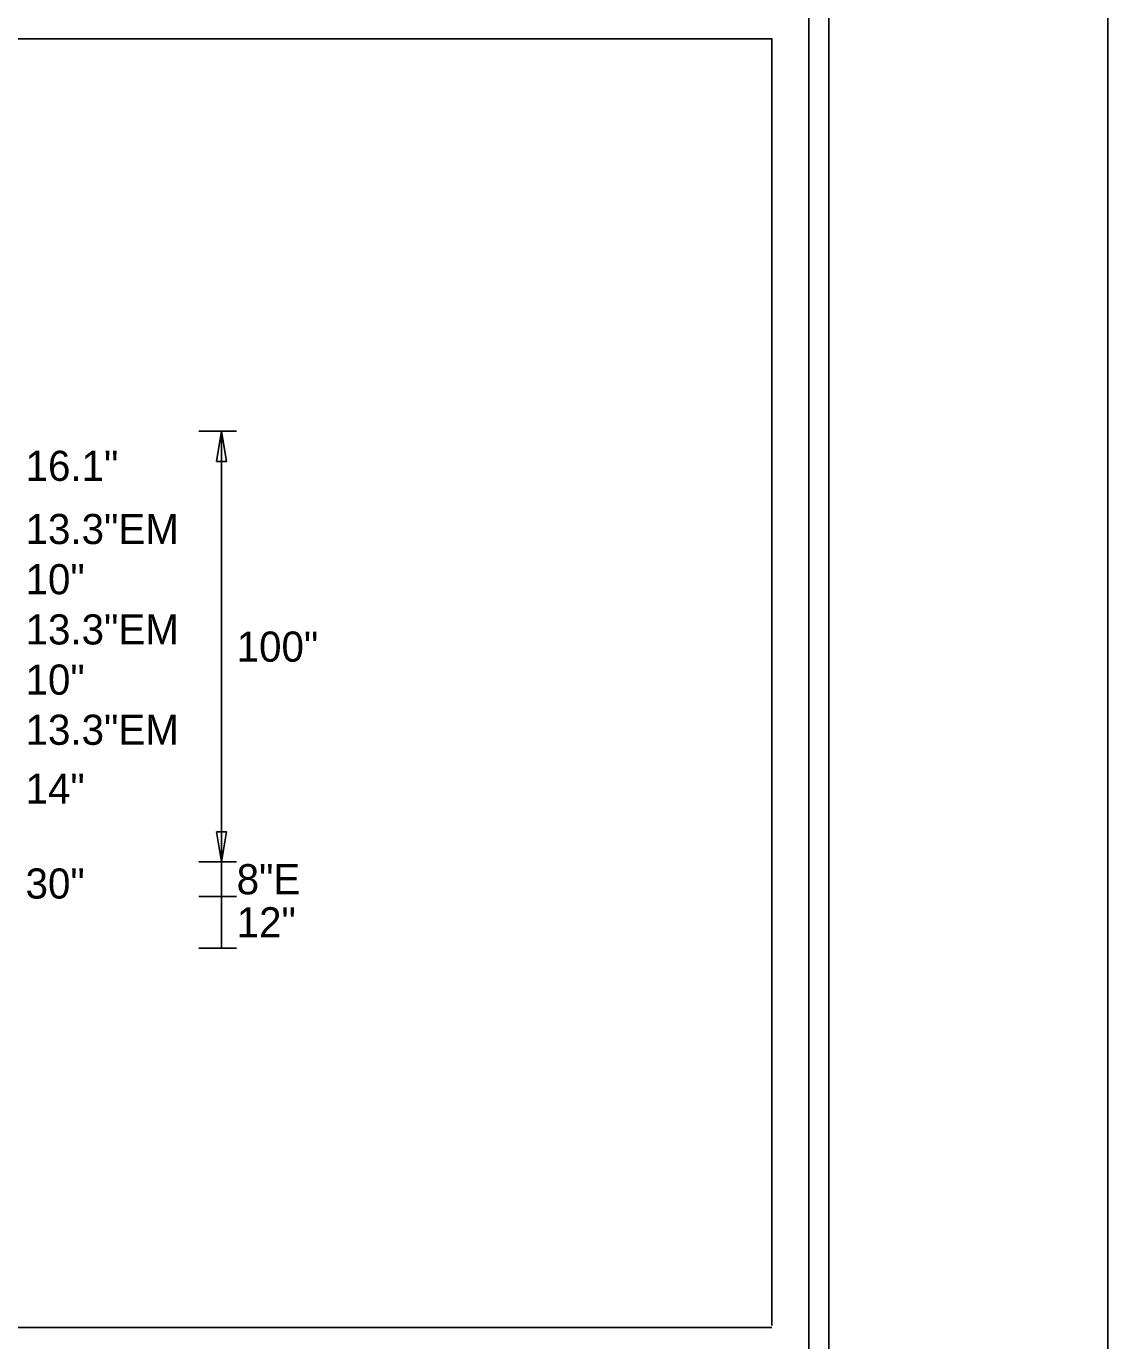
# Model space of a CAD drawing. Extents: x 17890628 to 17890817, y 17897493 to 17897992.
# Drawn here: x 17890796.4 to 17890817.32, y 17897520.28 to 17897545.71 of the extents above; entities that cross this region are included whole.
import ezdxf

# ---------------------------------------------------------------- set-up
doc = ezdxf.new("R2010")
doc.units = 0
for name, color, linetype in [('GSDims', 7, 'Continuous'), ('PlotBorder_dp', 7, 'Continuous'), ('SheetBorder_dp', 7, 'Continuous'), ('SheetLinesMisc1_dp', 7, 'Continuous'), ('SheetLinesMisc2_dp', 7, 'Continuous')]:
    doc.layers.add(name, color=color, linetype=linetype)

msp = doc.modelspace()

# ---------------------------------------------------------------- linework, layer by layer
at = {"layer": 'GSDims'}
for p, q in [((17890799.743, 17897537.876), (17890800.472, 17897537.876)), ((17890800.18, 17897529.543), (17890800.18, 17897537.876)), ((17890799.743, 17897529.543), (17890800.472, 17897529.543)), ((17890799.743, 17897529.543), (17890800.472, 17897529.543)), ((17890800.18, 17897529.543), (17890800.18, 17897528.876)), ((17890799.743, 17897528.876), (17890800.472, 17897528.876)), ((17890799.743, 17897528.876), (17890800.472, 17897528.876)), ((17890800.18, 17897527.876), (17890800.18, 17897528.876)), ((17890799.743, 17897527.876), (17890800.472, 17897527.876))]:
    msp.add_line(p, q, dxfattribs=at)
for points in [[(17890800.18, 17897537.876), (17890800.083, 17897537.293), (17890800.277, 17897537.293)], [(17890800.18, 17897529.543), (17890800.083, 17897530.126), (17890800.277, 17897530.126)]]:
    msp.add_lwpolyline(points, close=True, dxfattribs=at)
at = {"layer": 'PlotBorder_dp'}
msp.add_lwpolyline([(17890655.57, 17897492.839), (17890817.319, 17897492.839), (17890817.319, 17897596.75), (17890655.57, 17897596.75)], close=True, dxfattribs=at)
at = {"layer": 'SheetBorder_dp'}
msp.add_line((17890811.928, 17897595.77), (17890811.928, 17897493.819), dxfattribs=at)
at = {"layer": 'SheetLinesMisc1_dp'}
msp.add_line((17890736.825, 17897545.464), (17890810.827, 17897545.464), dxfattribs=at)
at = {"layer": 'SheetLinesMisc2_dp'}
for p, q in [((17890811.539, 17897502.033), (17890811.539, 17897595.69)), ((17890736.825, 17897545.464), (17890810.827, 17897545.464)), ((17890759.649, 17897545.464), (17890810.82, 17897545.464)), ((17890810.82, 17897520.574), (17890810.82, 17897545.464)), ((17890810.82, 17897523.401), (17890810.82, 17897523.435)), ((17890759.649, 17897520.539), (17890810.82, 17897520.539))]:
    msp.add_line(p, q, dxfattribs=at)

# ---------------------------------------------------------------- texts
at = {"layer": 'GSDims'}
for s, p in [('16.1"', (17890796.389, 17897536.916)), ('13.3"EM', (17890796.389, 17897535.693)), ('10"', (17890796.389, 17897534.722)), ('13.3"EM', (17890796.389, 17897533.751)), ('100"', (17890800.472, 17897533.418)), ('10"', (17890796.389, 17897532.78)), ('13.3"EM', (17890796.389, 17897531.81)), ('14"', (17890796.389, 17897530.67)), ('30"', (17890796.389, 17897528.835)), ('8"E', (17890800.472, 17897528.918)), ('12"', (17890800.472, 17897528.085))]:
    msp.add_text(s, height=0.5833, dxfattribs=at).set_placement(p)

doc.saveas('drawing.dxf')
